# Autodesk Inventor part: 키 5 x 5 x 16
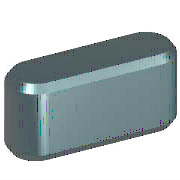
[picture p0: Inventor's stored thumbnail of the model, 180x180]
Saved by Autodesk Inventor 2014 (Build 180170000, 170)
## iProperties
IsCustomPart: 1
Created: 2012-02
Part Number: 키 5 x 5 x 16
Material: 강철, 연강
Description: 키 및 해당 키홈
Document SubType Name: Modeling
Standard: KS B 1311
Designer: mduedu
Standards Organization: KS
Language: ko-KR
Size Designation: 5 x 5 x 16
Categories: <MemberInstance><Categories><Category DisplayName="샤프트 부품" InternalName="7f7aeb1f-a693-4053-b835-cee3144e0d98" Mnemonic="SHFT"><Category DisplayName="키" Interna
Density: 1 g/cm^3
Appearance: Yellow
Author: mduedu
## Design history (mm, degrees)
sketch "스케치1"
  geometry: L1 (2.5, 2.5)-(13.5, 2.5); L2 (13.5, -2.5)-(2.5, -2.5); L3 (0, 9.4)-(0, -7.4) reference; L4 (-5, 0)-(30, 0) reference; L5 (16, 0)-(16, 7); A1 r 2.5 centre (2.5, 0) between (2.5, 2.5) and (2.5, -2.5); A2 r 2.5 centre (13.5, 0) between (13.5, -2.5) and (13.5, 2.5)
  constraints: 6 end point, 5 point on circle, 4 tangent, 3 point on line, 2 centre point, 1 horizontal, 1 parallel, 1 perpendicular
  dimensions: "d0" = 2.5 radius of A1 (= 0.5 x PB); "d13" = 2.5 radius of A2 (= 0.5 x PB); "d14" = 16 distance between parallel lines of L5 L3 (= NLG)
extrude "본체1" new body sketch "스케치1" taper "d3" = 0 deg; stored distance "d4" = 10
workplane "Work Plane3"
body "Solid1"
workplane "Work Plane1"
workplane "Work Plane2"
chamfer "모따기1" distance "d8" = 0.4 (= PHH); stored, may be unused: second distance "d9" = 0.4 (= PHH), angle "d15" = 45 deg
other parameters: "d1" = -3 (= -PNT), "d2" = 2 (= PH - PNT), "NLG" = 16 [user parameter; used in 3 equation terms], "PB" = 5 [user parameter; used in 2 equation terms], "PNT" = 3 [user parameter; used in 2 equation terms], "PH" = 5 [user parameter; used in 1 equation term], "PHH" = 0.4 [user parameter; used in 2 equation terms], "d10" = 0, "d16" = 0, "d17" = 0, "d18" = 0, "WDMIN" = 12 [user parameter], "PLB2" = 16 (= NLG) [user parameter], "WDMAX" = 17 [user parameter], "PLB1" = 16 (= NLG) [user parameter], "RR" = 0.16 [user parameter], "PUEB" = 2.3 [user parameter]
